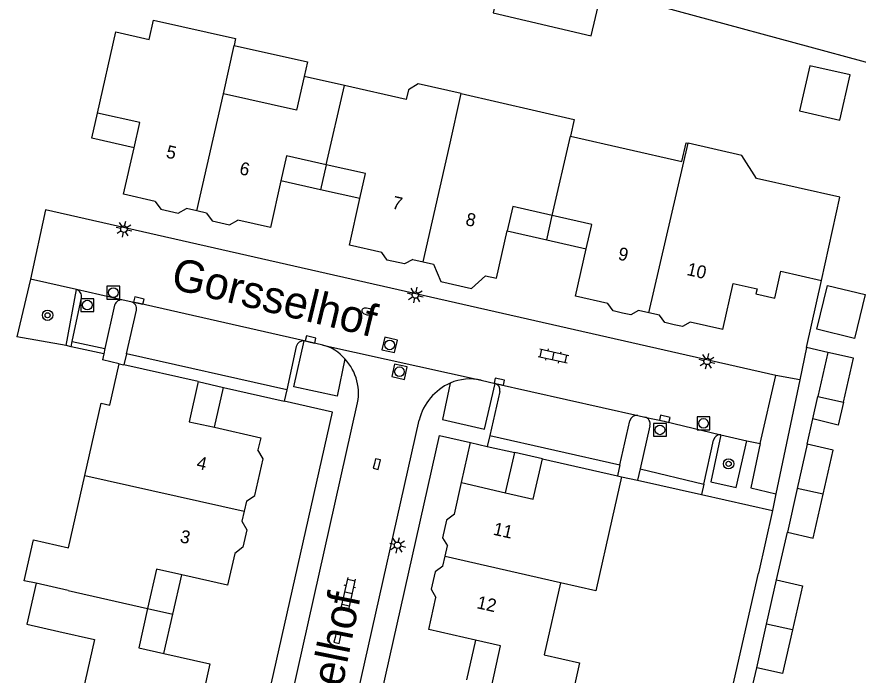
# Model space of a CAD drawing. Extents: x 128000 to 131008, y 398996 to 402500.
# Drawn here: x 128886.2 to 128951.5, y 399423.4 to 399474.5 of the extents above; entities that cross this region are included whole.
import ezdxf

# ---------------------------------------------------------------- set-up
doc = ezdxf.new("R2010")
doc.units = 0
for name, color, linetype in [('gg-afsc-erfafscheiding', 7, 'Continuous'), ('gg-afsc-haag', 7, 'Continuous'), ('gg-anno-huisnummerreeks BGT', 7, 'Continuous'), ('gg-anno-openbare ruimte label', 7, 'Continuous'), ('gg-bbg-bijgebouw', 7, 'Continuous'), ('gg-bbg-gedigitaliseerde bebouwing', 7, 'Continuous'), ('gg-bbg-gedigitaliseerde bijgebouw', 7, 'Continuous'), ('gg-bbg-hoofdgebouw', 7, 'Continuous'), ('gg-bbg-luifel en loopbrug', 7, 'Continuous'), ('gg-bbg-onder overbouw', 7, 'Continuous'), ('gg-bbg-pand overbouw', 7, 'Continuous'), ('gg-bbg-tussenscheiding', 7, 'Continuous'), ('gg-bbg-tussenscheiding niveau 01', 7, 'Continuous'), ('gg-knt-verharding', 7, 'Continuous'), ('gg-knt-verharding nz', 7, 'Continuous'), ('gt-grn-groengrens', 7, 'Continuous'), ('gt-grn-weggrens', 7, 'Continuous'), ('gt-symb-boom', 7, 'Continuous'), ('gt-symb-brandkraan', 7, 'Continuous'), ('gt-symb-klinker verharding', 7, 'Continuous'), ('gt-symb-kolk', 7, 'Continuous'), ('gt-symb-lichtmast', 7, 'Continuous'), ('gt-symb-rioolschacht', 7, 'Continuous')]:
    doc.layers.add(name, color=color, linetype=linetype)

# ---------------------------------------------------------------- blocks, each defined once
blk = doc.blocks.new('gt0-BOOM')
at = {"layer": 'gt-symb-boom'}
for radius in [0.4, 0.2]:
    blk.add_circle((0, 0), radius, dxfattribs=at)
blk = doc.blocks.new('gt0-RS')
at = {"layer": 'gt-symb-rioolschacht'}
blk.add_lwpolyline([(-0.5, -0.5), (0.5, -0.5), (0.5, 0.5), (-0.5, 0.5)], close=True, dxfattribs=at)
blk.add_circle((0, 0), 0.375, dxfattribs=at)
blk = doc.blocks.new('gt0-KOLK')
at = {"layer": 'gt-symb-kolk'}
blk.add_lwpolyline([(0, 0), (0.375, 0), (0.375, 0.4), (-0.375, 0.4), (-0.375, 0), (0, 0)], dxfattribs=at)
blk = doc.blocks.new('gt0-LMAST')
at = {"layer": 'gt-symb-lichtmast'}
for p, q in [((-0.182, 0.173), (-0.447, 0.438)), ((-0.005, 0.246), (-0.005, 0.621)), ((0.172, 0.173), (0.437, 0.438)), ((-0.255, -0.004), (-0.63, -0.004)), ((-0.182, -0.181), (-0.447, -0.446)), ((-0.005, -0.254), (-0.005, -0.629)), ((0.437, -0.446), (0.172, -0.181)), ((0.245, -0.004), (0.62, -0.004))]:
    blk.add_line(p, q, dxfattribs=at)
blk.add_circle((-0.005, -0.004), 0.25, dxfattribs=at)
blk = doc.blocks.new('gt0-KL1')
at = {"layer": 'gt-symb-klinker verharding'}
for p, q in [((-1.15, 0.3), (1.15, 0.3)), ((-1, -0.3), (-1, 0.3)), ((-0.5, 0.3), (-0.5, 0.45)), ((0, -0.3), (0, 0.3)), ((0.5, 0.3), (0.5, 0.45)), ((1, -0.3), (1, 0.3)), ((-1.15, -0.3), (1.15, -0.3)), ((-0.5, -0.45), (-0.5, -0.3)), ((0.5, -0.45), (0.5, -0.3))]:
    blk.add_line(p, q, dxfattribs=at)
blk = doc.blocks.new('gt0-BR')
at = {"layer": 'gt-symb-brandkraan'}
for centre, radius, start, end in [((-0.244, 0), 0.206, 107.56694, 252.43307), ((0.599, -2.664), 3, 106.89205, 107.56694), ((0, -0.691), 0.938, 73.10799, 106.89205), ((-0.599, -2.664), 3, 72.43309, 73.10799), ((0.244, 0), 0.206, 287.56695, 72.43309), ((0.599, 2.664), 3, 252.43307, 253.10797), ((0, 0.691), 0.938, 253.10797, 286.89206), ((-0.599, 2.664), 3, 286.89206, 287.56695)]:
    blk.add_arc(centre, radius, start, end, dxfattribs=at)

msp = doc.modelspace()

# ---------------------------------------------------------------- linework, layer by layer
at = {"layer": 'gg-afsc-erfafscheiding'}
for p, q in [((128962.286, 399468.182), (128891.298, 399487.444)), ((128947.475, 399448.802), (128948.646, 399454.015)), ((128947.475, 399448.802), (128946.951, 399446.309)), ((128949.131, 399448.427), (128947.475, 399448.802)), ((128946.951, 399446.309), (128945.09, 399437.46)), ((128947.538, 399441.303), (128947.971, 399443.265)), ((128933.12, 399438.78), (128934.362, 399438.504)), ((128934.362, 399438.504), (128939.332, 399437.398)), ((128939.332, 399437.398), (128944.85, 399436.17)), ((128944.85, 399436.17), (128943.746, 399431.293)), ((128945.158, 399430.778), (128945.992, 399434.476)), ((128936.886, 399400.95), (128943.746, 399431.293)), ((128942.776, 399420.243), (128943.612, 399423.951))]:
    msp.add_line(p, q, dxfattribs=at)
at = {"layer": 'gg-afsc-haag'}
msp.add_line((128890.027, 399448.967), (128886.193, 399449.625), dxfattribs=at)
at = {"layer": 'gg-bbg-bijgebouw'}
for p, q in [((128949.131, 399448.427), (128948.358, 399445.014)), ((128948.358, 399445.014), (128950.358, 399444.561)), ((128947.538, 399441.303), (128946.761, 399437.872)), ((128946.761, 399437.872), (128945.992, 399434.476))]:
    msp.add_line(p, q, dxfattribs=at)
for points in [[(128950.358, 399444.561), (128951.13, 399447.975), (128949.131, 399448.427)], [(128948.762, 399437.43), (128949.537, 399440.851), (128947.538, 399441.303)], [(128945.992, 399434.476), (128947.991, 399434.023), (128948.762, 399437.43)]]:
    msp.add_lwpolyline(points, dxfattribs=at)
at = {"layer": 'gg-bbg-gedigitaliseerde bebouwing'}
for p, q in [((128902.227, 399468.493), (128903.052, 399472.237)), ((128911.622, 399469.139), (128908.498, 399469.845)), ((128916.416, 399468.055), (128911.622, 399469.139))]:
    msp.add_line(p, q, dxfattribs=at)
for points in [[(128893.88, 399473.3), (128896.472, 399472.716), (128896.808, 399474.208), (128903.171, 399472.775), (128903.052, 399472.237)], [(128908.498, 399469.845), (128907.906, 399467.214), (128902.227, 399468.493)], [(128920.671, 399468.525), (128929.457, 399466.499), (128929.154, 399465.197)], [(128929.154, 399465.197), (128937.798, 399463.239), (128938.128, 399464.697)], [(128891.474, 399438.877), (128892.728, 399444.485), (128893.42, 399444.33)], [(128887.694, 399430.511), (128886.774, 399430.714), (128887.484, 399433.881), (128890.216, 399433.269), (128891.474, 399438.877)], [(128887.694, 399430.511), (128886.982, 399427.328), (128889.466, 399426.772)], [(128889.466, 399426.772), (128892.215, 399426.153), (128890.948, 399420.546)]]:
    msp.add_lwpolyline(points, dxfattribs=at)
at = {"layer": 'gg-bbg-gedigitaliseerde bijgebouw'}
for p, q in [((128944.381, 399427.347), (128945.158, 399430.778)), ((128943.612, 399423.951), (128944.381, 399427.347))]:
    msp.add_line(p, q, dxfattribs=at)
for points in [[(128946.946, 399467.162), (128950.068, 399466.459), (128950.859, 399469.971), (128947.737, 399470.674), (128946.946, 399467.162)], [(128949.107, 399453.621), (128952.023, 399452.916), (128951.2, 399449.514), (128948.284, 399450.219), (128949.107, 399453.621)], [(128945.158, 399430.778), (128947.157, 399430.326), (128946.382, 399426.905)], [(128946.382, 399426.905), (128945.611, 399423.498), (128943.612, 399423.951)]]:
    msp.add_lwpolyline(points, dxfattribs=at)
at = {"layer": 'gg-bbg-hoofdgebouw'}
for p, q in [((128892.46, 399466.99), (128893.88, 399473.3)), ((128938.128, 399464.697), (128938.293, 399464.66)), ((128900.163, 399459.413), (128899.363, 399459.594)), ((128900.919, 399459.242), (128900.163, 399459.413)), ((128923.42, 399454.18), (128924.255, 399457.867)), ((128916.915, 399455.646), (128917.719, 399455.465)), ((128935.253, 399451.503), (128934.445, 399451.685)), ((128936.074, 399451.318), (128935.253, 399451.503)), ((128940.98, 399450.21), (128938.443, 399450.783)), ((128893.42, 399444.33), (128894.14, 399447.55)), ((128894.14, 399447.55), (128894.508, 399447.466)), ((128900.27, 399446.16), (128894.508, 399447.466)), ((128926.98, 399440.17), (128932.798, 399438.853)), ((128933.12, 399438.78), (128932.4, 399435.56)), ((128932.798, 399438.853), (128933.12, 399438.78)), ((128920.153, 399435.873), (128920.7, 399438.33)), ((128920.7, 399438.33), (128924.123, 399437.537)), ((128904.013, 399436.884), (128903.836, 399436.096)), ((128903.836, 399436.096), (128903.663, 399435.325)), ((128919.43, 399432.625), (128919.605, 399433.412)), ((128919.254, 399431.834), (128919.43, 399432.625))]:
    msp.add_line(p, q, dxfattribs=at)
for points in [[(128920.671, 399468.525), (128917.344, 399469.267), (128916.58, 399468.792), (128916.416, 399468.055)], [(128895.291, 399464.309), (128895.73, 399466.26), (128892.46, 399466.99)], [(128896.926, 399460.146), (128894.48, 399460.7), (128895.291, 399464.309)], [(128948.646, 399454.015), (128950.075, 399460.466), (128943.601, 399461.921), (128942.469, 399463.715), (128938.293, 399464.66)], [(128910.208, 399462.99), (128907.11, 399463.68), (128906.678, 399461.742)], [(128912.825, 399460.358), (128913.26, 399462.31), (128910.208, 399462.99)], [(128906.678, 399461.742), (128905.87, 399458.12), (128903.347, 399458.692)], [(128914.51, 399456.189), (128912.02, 399456.75), (128912.825, 399460.358)], [(128896.926, 399460.146), (128897.359, 399459.545), (128898.717, 399459.23), (128899.363, 399459.594)], [(128900.919, 399459.242), (128901.346, 399458.649), (128902.704, 399458.334), (128903.347, 399458.692)], [(128932.066, 399452.222), (128929.55, 399452.79), (128930.386, 399456.477)], [(128916.915, 399455.646), (128916.281, 399455.288), (128914.923, 399455.592), (128914.51, 399456.189)], [(128917.719, 399455.465), (128918.535, 399455.281), (128919.106, 399453.928), (128921.48, 399453.388), (128922.577, 399454.37), (128923.42, 399454.18)], [(128940.98, 399450.21), (128941.786, 399453.78), (128943.639, 399453.362), (128943.551, 399452.972), (128945.014, 399452.641), (128945.486, 399454.729), (128948.646, 399454.015)], [(128934.445, 399451.685), (128933.845, 399451.343), (128933.209, 399451.48), (128932.478, 399451.646), (128932.066, 399452.222)], [(128938.443, 399450.783), (128937.847, 399450.442), (128937.211, 399450.579), (128936.48, 399450.745), (128936.074, 399451.318)], [(128900.27, 399446.16), (128899.58, 399443.05), (128901.532, 399442.613)], [(128901.532, 399442.613), (128905.12, 399441.81), (128904.91, 399440.875)], [(128904.013, 399436.884), (128904.669, 399437.33), (128905.302, 399440.174), (128904.91, 399440.875)], [(128920.153, 399435.873), (128919.549, 399435.413), (128919.242, 399434.051), (128919.605, 399433.412)], [(128932.4, 399435.56), (128931.139, 399429.919), (128928.384, 399430.535)], [(128903.663, 399435.325), (128904.036, 399434.668), (128903.74, 399433.309), (128903.101, 399432.822)], [(128903.101, 399432.822), (128902.55, 399430.37), (128898.989, 399431.17)], [(128898.989, 399431.17), (128897.03, 399431.61), (128896.347, 399428.559)], [(128919.254, 399431.834), (128918.662, 399431.411), (128918.355, 399430.049), (128918.715, 399429.414)], [(128928.384, 399430.535), (128927.131, 399424.964), (128929.874, 399424.347), (128929.162, 399421.181)], [(128921.789, 399426.101), (128918.16, 399426.92), (128918.715, 399429.414)], [(128896.347, 399428.559), (128895.66, 399425.49), (128897.611, 399425.052)], [(128923.045, 399422.568), (128923.74, 399425.66), (128921.789, 399426.101)], [(128897.611, 399425.052), (128901.18, 399424.25), (128900.631, 399421.8)]]:
    msp.add_lwpolyline(points, dxfattribs=at)
at = {"layer": 'gg-bbg-luifel en loopbrug'}
for p, q in [((128910.208, 399462.99), (128909.77, 399461.046)), ((128909.77, 399461.046), (128906.678, 399461.742)), ((128912.825, 399460.358), (128909.77, 399461.046)), ((128900.27, 399446.16), (128902.231, 399445.716)), ((128901.532, 399442.613), (128902.231, 399445.716)), ((128947.971, 399443.265), (128948.358, 399445.014)), ((128920.7, 399438.33), (128921.398, 399441.427)), ((128921.398, 399441.427), (128922.708, 399441.132)), ((128922.708, 399441.132), (128924.844, 399440.651)), ((128898.302, 399428.119), (128898.989, 399431.17)), ((128896.347, 399428.559), (128898.302, 399428.119)), ((128897.611, 399425.052), (128898.302, 399428.119)), ((128921.789, 399426.101), (128921.093, 399423.008))]:
    msp.add_line(p, q, dxfattribs=at)
for points in [[(128923.173, 399474.775), (128930.775, 399473.005), (128931.546, 399476.317), (128923.944, 399478.086), (128923.173, 399474.775)], [(128903.052, 399472.237), (128908.749, 399470.982), (128908.498, 399469.845)], [(128895.291, 399464.309), (128892.022, 399465.045), (128892.46, 399466.99)], [(128950.358, 399444.561), (128949.93, 399442.791), (128947.971, 399443.265)]]:
    msp.add_lwpolyline(points, dxfattribs=at)
at = {"layer": 'gg-bbg-onder overbouw'}
for p, q in [((128930.81, 399458.35), (128927.752, 399459.043)), ((128930.386, 399456.477), (128930.81, 399458.35))]:
    msp.add_line(p, q, dxfattribs=at)
for points in [[(128927.752, 399459.043), (128924.679, 399459.739), (128924.255, 399457.867)], [(128924.123, 399437.537), (128926.27, 399437.04), (128926.98, 399440.17)]]:
    msp.add_lwpolyline(points, dxfattribs=at)
at = {"layer": 'gg-bbg-pand overbouw'}
for p, q in [((128924.255, 399457.867), (128927.325, 399457.171)), ((128927.325, 399457.171), (128930.386, 399456.477)), ((128924.123, 399437.537), (128924.844, 399440.651)), ((128926.98, 399440.17), (128924.844, 399440.651))]:
    msp.add_line(p, q, dxfattribs=at)
at = {"layer": 'gg-bbg-tussenscheiding'}
for p, q in [((128910.208, 399462.99), (128911.622, 399469.139)), ((128900.163, 399459.413), (128902.227, 399468.493)), ((128927.752, 399459.043), (128929.154, 399465.197)), ((128935.253, 399451.503), (128938.293, 399464.66)), ((128891.474, 399438.877), (128903.836, 399436.096)), ((128948.762, 399437.43), (128946.761, 399437.872)), ((128890.181, 399429.95), (128887.694, 399430.511)), ((128890.181, 399429.95), (128896.347, 399428.559)), ((128946.382, 399426.905), (128944.381, 399427.347))]:
    msp.add_line(p, q, dxfattribs=at)
for points in [[(128917.719, 399455.465), (128919.775, 399464.432), (128920.671, 399468.525)], [(128919.43, 399432.625), (128928.393, 399430.573), (128928.384, 399430.535)]]:
    msp.add_lwpolyline(points, dxfattribs=at)
at = {"layer": 'gg-bbg-tussenscheiding niveau 01'}
msp.add_line((128927.325, 399457.171), (128927.752, 399459.043), dxfattribs=at)
at = {"layer": 'gg-knt-verharding'}
for p, q in [((128890.82, 399453.305), (128887.25, 399454.12)), ((128890.027, 399448.967), (128890.82, 399453.305)), ((128890.478, 399449.28), (128891.205, 399452.65)), ((128895.047, 399452.348), (128894.439, 399452.489)), ((128893.779, 399452.092), (128893.036, 399448.729)), ((128894.699, 399448.307), (128895.478, 399451.7)), ((128890.421, 399448.856), (128890.478, 399449.28)), ((128890.478, 399449.28), (128893.036, 399448.729)), ((128890.421, 399448.856), (128890.027, 399448.967)), ((128892.955, 399448.32), (128890.421, 399448.856)), ((128893.036, 399448.729), (128892.955, 399448.32)), ((128907.884, 399448.897), (128907.149, 399445.522)), ((128892.955, 399448.32), (128892.847, 399447.843)), ((128894.14, 399447.55), (128892.847, 399447.843)), ((128894.699, 399448.307), (128894.508, 399447.466)), ((128907.149, 399445.522), (128894.699, 399448.307)), ((128943.89, 399441.36), (128945.09, 399446.63)), ((128922.239, 399446.279), (128923.329, 399446.023)), ((128902.231, 399445.716), (128906.951, 399444.648)), ((128907.149, 399445.522), (128906.951, 399444.648)), ((128923.667, 399445.393), (128922.899, 399441.983)), ((128904.339, 399407.452), (128912.581, 399444.271)), ((128934.399, 399443.525), (128934.93, 399443.414)), ((128909.147, 399406.352), (128917.42, 399443.18)), ((128932.993, 399439.714), (128933.765, 399443.118)), ((128935.319, 399442.73), (128934.557, 399439.38)), ((128922.899, 399441.983), (128922.708, 399441.132)), ((128922.899, 399441.983), (128932.993, 399439.714)), ((128940.823, 399442.039), (128942.855, 399441.578)), ((128939.511, 399438.206), (128940.272, 399441.614)), ((128942.855, 399441.578), (128943.89, 399441.36)), ((128932.993, 399439.714), (128932.798, 399438.853)), ((128934.557, 399439.38), (128934.362, 399438.504)), ((128934.557, 399439.38), (128939.511, 399438.206)), ((128939.511, 399438.206), (128939.332, 399437.398)), ((128945.09, 399437.46), (128944.85, 399436.17))]:
    msp.add_line(p, q, dxfattribs=at)
for points in [[(128945.09, 399446.63), (128888.41, 399459.48), (128887.25, 399454.12)], [(128911.648, 399447.927), (128911.045, 399445.026), (128907.698, 399445.752), (128908.488, 399449.33)], [(128909.944, 399448.977), (128908.946, 399449.231), (128908.488, 399449.33)], [(128919.833, 399446.05), (128919.229, 399443.221), (128922.485, 399442.478), (128923.329, 399446.023)], [(128901.99, 399405.23), (128910.7, 399443.8), (128906.951, 399444.648)], [(128910.32, 399403.37), (128918.99, 399441.97), (128921.398, 399441.427)], [(128940.823, 399442.039), (128940.059, 399438.387), (128942.022, 399437.947), (128942.855, 399441.578)], [(128943.89, 399441.36), (128943.16, 399437.93), (128945.09, 399437.46)]]:
    msp.add_lwpolyline(points, dxfattribs=at)
for centre, radius, start, end in [((128890.656, 399452.768), 0.561, 347.86818, 73.02467), ((128894.319, 399451.941), 0.561, 77.63108, 164.42402), ((128894.936, 399451.807), 0.553, 348.88279, 78.37484), ((128908.449, 399448.747), 0.585, 86.17312, 165.09941), ((128909.29, 399446.008), 3.041, 39.14229, 77.5752), ((128908.819, 399445.258), 3.889, 345.29807, 43.33422), ((128921.566, 399442.143), 4.274, 113.9249, 165.9631), ((128921.394, 399442.403), 3.967, 77.70028, 113.17364), ((128923.128, 399445.509), 0.552, 347.81239, 68.61543), ((128934.297, 399442.987), 0.547, 79.21877, 166.17857), ((128934.789, 399442.881), 0.551, 344.08362, 75.17132), ((128940.776, 399441.53), 0.511, 84.73602, 170.55177)]:
    msp.add_arc(centre, radius, start, end, dxfattribs=at)
at = {"layer": 'gg-knt-verharding nz'}
for p, q in [((128894.439, 399452.489), (128890.82, 399453.305)), ((128923.329, 399446.023), (128934.399, 399443.525))]:
    msp.add_line(p, q, dxfattribs=at)
for points in [[(128908.488, 399449.33), (128895.619, 399452.255), (128895.047, 399452.348)], [(128934.93, 399443.414), (128936.43, 399443.086), (128940.823, 399442.039)]]:
    msp.add_lwpolyline(points, dxfattribs=at)
at = {"layer": 'gt-grn-groengrens'}
for p, q in [((128887.25, 399454.12), (128886.193, 399449.625)), ((128946.951, 399446.309), (128945.09, 399446.63))]:
    msp.add_line(p, q, dxfattribs=at)
at = {"layer": 'gt-grn-weggrens'}
msp.add_line((128909.944, 399448.977), (128922.239, 399446.279), dxfattribs=at)

# ---------------------------------------------------------------- block references
at = {"layer": 'gt-symb-boom'}
for p in [(128888.581, 399451.308), (128941.436, 399439.781)]:
    msp.add_blockref('gt0-BOOM', p, dxfattribs=at)
at = {"layer": 'gt-symb-brandkraan', "rotation": -12.77124256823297}
msp.add_blockref('gt0-BR', (128913.411, 399451.595), dxfattribs=at)
at = {"layer": 'gt-symb-klinker verharding'}
for p, rotation in [((128927.841, 399448.154), -12.771242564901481), ((128911.94, 399429.767), 77.35314650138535)]:
    msp.add_blockref('gt0-KL1', p, dxfattribs=dict(at, rotation=rotation))
at = {"layer": 'gt-symb-kolk'}
for p, rotation in [((128895.619, 399452.255), -12.808916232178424), ((128908.946, 399449.231), -14.269151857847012), ((128923.595, 399445.968), -12.742384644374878), ((128936.43, 399443.086), -13.40408572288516), ((128913.939, 399439.807), -102.71533698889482), ((128910.891, 399426.296), -102.71533698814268)]:
    msp.add_blockref('gt0-KOLK', p, dxfattribs=dict(at, rotation=rotation))
at = {"layer": 'gt-symb-lichtmast'}
for p, rotation in [((128894.511, 399457.993), -12.771242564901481), ((128917.124, 399452.872), -102.71533698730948), ((128939.771, 399447.733), -12.771242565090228), ((128915.745, 399433.455), -102.71533698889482)]:
    msp.add_blockref('gt0-LMAST', p, dxfattribs=dict(at, rotation=rotation))
at = {"layer": 'gt-symb-rioolschacht'}
for p in [(128893.686, 399453.068), (128891.66, 399452.097), (128939.486, 399442.915), (128936.101, 399442.418)]:
    msp.add_blockref('gt0-RS', p, dxfattribs=at)
at = {"layer": 'gt-symb-rioolschacht', "rotation": -12.771242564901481}
for p in [(128915.13, 399449.009), (128915.89, 399446.924)]:
    msp.add_blockref('gt0-RS', p, dxfattribs=at)

# ---------------------------------------------------------------- texts
at = {"layer": 'gg-anno-huisnummerreeks BGT'}
for s, rotation, p in [('5', 347.2, (128897.716, 399463.556)), ('6', 347.2, (128903.411, 399462.266)), ('7', 347.3, (128915.26, 399459.607)), ('8', 347.3, (128920.96, 399458.322)), ('9', 347.3, (128932.793, 399455.645)), ('10', 347.3, (128938.129, 399454.441)), ('4', 347.3, (128900.086, 399439.427)), ('11', 347.4, (128923.102, 399434.289)), ('3', 347.3, (128898.801, 399433.707)), ('12', 347.4, (128921.832, 399428.584))]:
    msp.add_text(s, height=1, rotation=rotation, dxfattribs=at).set_placement(p)
at = {"layer": 'gg-anno-openbare ruimte label'}
for rotation, p in [(346.4, (128898.051, 399453.409)), (78.6, (128909.691, 399413.66))]:
    msp.add_text('Gorsselhof', height=2.5, rotation=rotation, dxfattribs=at).set_placement(p)

doc.saveas('drawing.dxf')
